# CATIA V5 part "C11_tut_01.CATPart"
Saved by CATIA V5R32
Part number: Part1
Bounding box of the stored display mesh (mm): x -74.368 to 0, y -50 to 50, z -100 to 0
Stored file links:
  D:\PROJECTS\Project 2022\CATIA V5 6R 2022\Resources\Tutorial Files\c11_catia_v5_6r2022_tut\C11_tut_01.CATPart
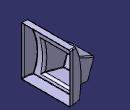
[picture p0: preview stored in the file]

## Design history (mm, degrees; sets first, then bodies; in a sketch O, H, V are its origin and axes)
Body1 (main body)
  Sketch1 on zx-plane, origin (0, 0, 0), H (-1, 0, 0), V (0, 0, 1)
    line L1 (0, 0) -> (12, 0)
    arc A1 centre (-96.8872, -61.3887) radius 125 from (12, 0) to (22, -100) cw
    line L2 (22, -100) -> (0, -100)
    point P4 (0, -100)
    length L1 = 12
    length L2 = 22
    distance L1 L2 = 100
    radius A1 = 125
    horizontal: L1 H, L2 H
    coincidence: P4 V
  Extrude1: Element1 Sketch1, Lim1 50, Lim2 50
  Sketch2 on zx-plane, origin (0, 0, 0), H (-1, 0, 0), V (0, 0, 1)
    line L1 (20, -40) -> (74.9495, -60)
    point P1 (20, -40)
    point P2 (74.9495, -60)
    reference projected line E1 (22, -100) -> (0, -100) from edge of Extrude1
    distance P2 H = 60
    distance P1 E1 = 60
    distance V P1 = 20
    angle L1 H = 20
  Plane1: type Normal, Curve Sketch2, RefPoint Sketch2.P2, Ratio 0
  Sketch3 on Plane1, origin (-85.4657, 0, -31.107), H (0, -1, 0), V (-0.342, 0, 0.9397)
    point P1 (-25, -30.7473)
    line L1 (-25, -30.7473) -> (25, -30.7473)
    line L2 (25, -30.7473) -> (25, -70.7473)
    line L3 (25, -70.7473) -> (-25, -70.7473)
    line L4 (-25, -70.7473) -> (-25, -30.7473)
    point P2 (25, -30.7473)
    reference projected point E1 (0, -30.7473) from Sketch2.P2
    axis line L5 (0, 21.6916) -> (0, -100.0328)
    point P5 (0, 21.6916)
    length L3 = 50
    length L2 = 40
    horizontal: L1 H, L3 H
    vertical: L2 V, L4 V, L5 V
    coincidence: L1 E1, P5 V
    symmetry: P1 P2 L5
  Plane2: type Normal, Curve Sketch2, RefPoint Sketch2.P1, Ratio 0
  Sketch4 on Plane2, origin (-30.5162, 0, -11.107), H (0, -1, 0), V (-0.342, 0, 0.9397)
    line L1 (-32.5, -21.2473) -> (32.5, -21.2473)
    line L2 (32.5, -21.2473) -> (32.5, -81.2473)
    line L3 (32.5, -81.2473) -> (-32.5, -81.2473)
    line L4 (-32.5, -81.2473) -> (-32.5, -21.2473)
    reference projected line E1 (25, -30.7473) -> (-25, -30.7473) from Sketch3.L1
    distance E1 L1 = 9.5
    distance V L2 = 32.5
    length L3 = 65
    length L2 = 60
    horizontal: L1 H, L3 H
    vertical: L2 V, L4 V
  Loft1: Sections (Sketch3; Sketch4), SectionCouplingPoints ({coupling CouplingPoints (vertex [element of Sketch3 | element of Sketch3]; vertex [element of Sketch4 | element of Sketch4])}; {coupling CouplingPoints (vertex [element of Sketch3 | element of Sketch3]; vertex [element of Sketch4 | element of Sketch4])}; {coupling CouplingPoints (vertex [element of Sketch3 | element of Sketch3]; vertex [element of Sketch4 | element of Sketch4])}; {coupling CouplingPoints (vertex [element of Sketch3 | element of Sketch3]; vertex [element of Sketch4 | element of Sketch4])})
  Sketch5 on face of Extrude1 from Sketch1.L1, origin (0, 0, 0), H (1, 0, 0), V (0, -1, 0)
    point P1 (0, -50)
    line L1 (0, -50) -> (-5, -50)
    reference projected point E1 (0, -50) from vertex [face of Extrude1 from Sketch1.L2]
    arc A1 centre (-5, 0) radius 50 from (-5, -50) to (-35.922, -39.2916) cw
    length L1 = 5
    radius A1 = 50
    horizontal: L1 H
    coincidence: P1 E1
    tangency: A1 L1
  Extrude2: Element1 Sketch5, Lim1 100, Lim2 0
  Symmetry1: ToTransfor Extrude2, Reference zx-plane
  Trim1: Trimmed (Extrude2; Extrude1)
  Trim2: Trimmed (Trim1; Symmetry1)
  Trim3: Trimmed (Loft1; Trim2)
  CloseSurface1: CloseElement Trim3
  Sketch6 on face of CloseSurface1, origin (-85.4657, 0, -31.107), H (0, -1, 0), V (-0.342, 0, 0.9397)
    line L1 (-20, -55.7473) -> (0, -55.7473)
    line L2 (0, -55.7473) -> (0, -65.7473)
    line L3 (0, -65.7473) -> (-20, -65.7473)
    line L4 (-20, -65.7473) -> (-20, -55.7473)
    reference projected line E1 (-25, -70.7473) -> (25, -70.7473) from edge [face of CloseSurface1 | face of CloseSurface1]
    reference projected line E2 (-25, -30.7473) -> (-25, -70.7473) from edge [face of CloseSurface1 | face of CloseSurface1]
    length L1 = 20
    length L4 = 10
    distance L3 E1 = 5
    distance L4 E2 = 5
    horizontal: L1 H, L3 H
    vertical: L2 V, L4 V
  Pocket1: profile Sketch6, direction (0.9397, 0, 0.342), length 5
  Fillet1: radius 1, on edge [face of CloseSurface1 | face of Pocket1 from Sketch6.L1]; edge [face of CloseSurface1 | face of Pocket1 from Sketch6.L2]; edge [face of CloseSurface1 | face of Pocket1 from Sketch6.L3]; edge [face of CloseSurface1 | face of Pocket1 from Sketch6.L4]; face of Pocket1 from Sketch6.L1; edge [face of Pocket1 from Sketch6.L1 | face of Pocket1 from Sketch6.L2]; edge [face of Pocket1 from Sketch6.L2 | end face of Pocket1]; edge [face of Pocket1 from Sketch6.L2 | face of Pocket1 from Sketch6.L3]; edge [face of Pocket1 from Sketch6.L3 | end face of Pocket1]; edge [face of Pocket1 from Sketch6.L3 | face of Pocket1 from Sketch6.L4]; edge [face of Pocket1 from Sketch6.L4 | end face of Pocket1]
  Fillet2: radius 3.5, on edge [face of CloseSurface1 | face of CloseSurface1] (x4)
  Fillet3: radius 2, on edge [face of CloseSurface1 | face of CloseSurface1] (x12)
  Fillet4: radius 2, on edge [face of CloseSurface1 | face of CloseSurface1] (x5); edge [face of CloseSurface1 | face of Fillet3]
  Shell1: ExtOffset 0, Face face of CloseSurface1, IntOffset 1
